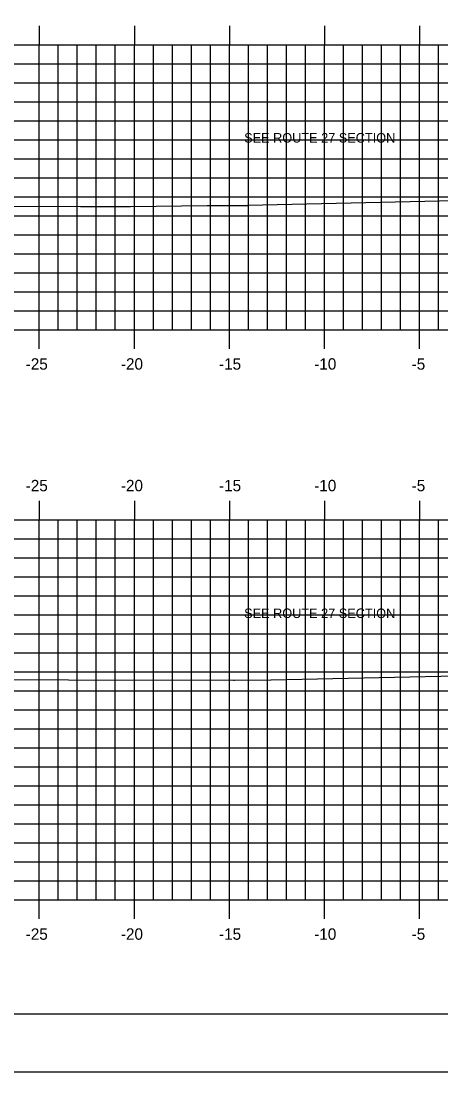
# Model space of a CAD drawing. Extents: x 1048343 to 1048513, y 781387 to 781497.
# Drawn here: x 1048400.2 to 1048422.3, y 781387.3 to 781442.6 of the extents above; entities that cross this region are included whole.
import ezdxf

# ---------------------------------------------------------------- set-up
doc = ezdxf.new("R2010")
doc.units = 0
for name, color, linetype in [('ANNOTATION', 7, 'Continuous'), ('BORDER', 7, 'Continuous'), ('H_V ANNOTATION', 7, 'Continuous'), ('MAJOR', 7, 'Continuous'), ('MINOR', 7, 'Continuous'), ('PLOT BOUNDARY', 7, 'Continuous'), ('S_Roadway_Centerline', 7, 'Continuous')]:
    doc.layers.add(name, color=color, linetype=linetype)

msp = doc.modelspace()

# ---------------------------------------------------------------- linework, layer by layer
at = {"layer": 'BORDER'}
msp.add_lwpolyline([(1048351.12, 781390.375), (1048511.12, 781390.375), (1048511.12, 781495.375), (1048351.12, 781495.375)], close=True, dxfattribs=at)
at = {"layer": 'MAJOR'}
for p, q in [((1048401.119, 781442.377), (1048401.119, 781441.375)), ((1048406.119, 781442.377), (1048406.119, 781441.375)), ((1048411.119, 781442.377), (1048411.119, 781441.375)), ((1048416.119, 781442.377), (1048416.119, 781441.375)), ((1048421.119, 781442.377), (1048421.119, 781441.375)), ((1048356.119, 781441.375), (1048496.119, 781441.375)), ((1048356.119, 781441.375), (1048496.119, 781441.375)), ((1048401.119, 781426.375), (1048401.119, 781441.375)), ((1048406.119, 781426.375), (1048406.119, 781441.375)), ((1048411.119, 781426.375), (1048411.119, 781441.375)), ((1048416.119, 781426.375), (1048416.119, 781441.375)), ((1048421.119, 781426.375), (1048421.119, 781441.375)), ((1048356.119, 781436.375), (1048496.119, 781436.375)), ((1048356.119, 781431.375), (1048496.119, 781431.375)), ((1048356.119, 781426.375), (1048496.119, 781426.375)), ((1048356.119, 781426.375), (1048496.119, 781426.375)), ((1048401.119, 781425.373), (1048401.119, 781426.375)), ((1048406.119, 781425.373), (1048406.119, 781426.375)), ((1048411.119, 781425.373), (1048411.119, 781426.375)), ((1048416.119, 781425.373), (1048416.119, 781426.375)), ((1048421.119, 781425.373), (1048421.119, 781426.375)), ((1048401.119, 781417.377), (1048401.119, 781416.375)), ((1048406.119, 781417.377), (1048406.119, 781416.375)), ((1048411.119, 781417.377), (1048411.119, 781416.375)), ((1048416.119, 781417.377), (1048416.119, 781416.375)), ((1048421.119, 781417.377), (1048421.119, 781416.375)), ((1048356.119, 781416.375), (1048496.119, 781416.375)), ((1048356.119, 781416.375), (1048496.119, 781416.375)), ((1048401.119, 781396.375), (1048401.119, 781416.375)), ((1048406.119, 781396.375), (1048406.119, 781416.375)), ((1048411.119, 781396.375), (1048411.119, 781416.375)), ((1048416.119, 781396.375), (1048416.119, 781416.375)), ((1048421.119, 781396.375), (1048421.119, 781416.375)), ((1048356.119, 781411.375), (1048496.119, 781411.375)), ((1048356.119, 781406.375), (1048496.119, 781406.375)), ((1048356.119, 781401.375), (1048496.119, 781401.375)), ((1048356.119, 781396.375), (1048496.119, 781396.375)), ((1048356.119, 781396.375), (1048496.119, 781396.375)), ((1048401.119, 781395.373), (1048401.119, 781396.375)), ((1048406.119, 781395.373), (1048406.119, 781396.375)), ((1048411.119, 781395.373), (1048411.119, 781396.375)), ((1048416.119, 781395.373), (1048416.119, 781396.375)), ((1048421.119, 781395.373), (1048421.119, 781396.375))]:
    msp.add_line(p, q, dxfattribs=at)
at = {"layer": 'MINOR'}
for p, q in [((1048402.119, 781426.375), (1048402.119, 781441.375)), ((1048403.119, 781426.375), (1048403.119, 781441.375)), ((1048404.119, 781426.375), (1048404.119, 781441.375)), ((1048405.119, 781426.375), (1048405.119, 781441.375)), ((1048407.119, 781426.375), (1048407.119, 781441.375)), ((1048408.119, 781426.375), (1048408.119, 781441.375)), ((1048409.119, 781426.375), (1048409.119, 781441.375)), ((1048410.119, 781426.375), (1048410.119, 781441.375)), ((1048412.119, 781426.375), (1048412.119, 781441.375)), ((1048413.119, 781426.375), (1048413.119, 781441.375)), ((1048414.119, 781426.375), (1048414.119, 781441.375)), ((1048415.119, 781426.375), (1048415.119, 781441.375)), ((1048417.119, 781426.375), (1048417.119, 781441.375)), ((1048418.119, 781426.375), (1048418.119, 781441.375)), ((1048419.119, 781426.375), (1048419.119, 781441.375)), ((1048420.119, 781426.375), (1048420.119, 781441.375)), ((1048422.119, 781426.375), (1048422.119, 781441.375)), ((1048356.119, 781440.375), (1048496.119, 781440.375)), ((1048356.119, 781439.375), (1048496.119, 781439.375)), ((1048356.119, 781438.375), (1048496.119, 781438.375)), ((1048356.119, 781437.375), (1048496.119, 781437.375)), ((1048356.119, 781435.375), (1048496.119, 781435.375)), ((1048356.119, 781434.375), (1048496.119, 781434.375)), ((1048356.119, 781433.375), (1048496.119, 781433.375)), ((1048356.119, 781432.375), (1048496.119, 781432.375)), ((1048356.119, 781430.375), (1048496.119, 781430.375)), ((1048356.119, 781429.375), (1048496.119, 781429.375)), ((1048356.119, 781428.375), (1048496.119, 781428.375)), ((1048356.119, 781427.375), (1048496.119, 781427.375)), ((1048402.119, 781396.375), (1048402.119, 781416.375)), ((1048403.119, 781396.375), (1048403.119, 781416.375)), ((1048404.119, 781396.375), (1048404.119, 781416.375)), ((1048405.119, 781396.375), (1048405.119, 781416.375)), ((1048407.119, 781396.375), (1048407.119, 781416.375)), ((1048408.119, 781396.375), (1048408.119, 781416.375)), ((1048409.119, 781396.375), (1048409.119, 781416.375)), ((1048410.119, 781396.375), (1048410.119, 781416.375)), ((1048412.119, 781396.375), (1048412.119, 781416.375)), ((1048413.119, 781396.375), (1048413.119, 781416.375)), ((1048414.119, 781396.375), (1048414.119, 781416.375)), ((1048415.119, 781396.375), (1048415.119, 781416.375)), ((1048417.119, 781396.375), (1048417.119, 781416.375)), ((1048418.119, 781396.375), (1048418.119, 781416.375)), ((1048419.119, 781396.375), (1048419.119, 781416.375)), ((1048420.119, 781396.375), (1048420.119, 781416.375)), ((1048422.119, 781396.375), (1048422.119, 781416.375)), ((1048356.119, 781415.375), (1048496.119, 781415.375)), ((1048356.119, 781414.375), (1048496.119, 781414.375)), ((1048356.119, 781413.375), (1048496.119, 781413.375)), ((1048356.119, 781412.375), (1048496.119, 781412.375)), ((1048356.119, 781410.375), (1048496.119, 781410.375)), ((1048356.119, 781409.375), (1048496.119, 781409.375)), ((1048356.119, 781408.375), (1048496.119, 781408.375)), ((1048356.119, 781407.375), (1048496.119, 781407.375)), ((1048356.119, 781405.375), (1048496.119, 781405.375)), ((1048356.119, 781404.375), (1048496.119, 781404.375)), ((1048356.119, 781403.375), (1048496.119, 781403.375)), ((1048356.119, 781402.375), (1048496.119, 781402.375)), ((1048356.119, 781400.375), (1048496.119, 781400.375)), ((1048356.119, 781399.375), (1048496.119, 781399.375)), ((1048356.119, 781398.375), (1048496.119, 781398.375)), ((1048356.119, 781397.375), (1048496.119, 781397.375))]:
    msp.add_line(p, q, dxfattribs=at)
at = {"layer": 'PLOT BOUNDARY'}
msp.add_lwpolyline([(1048343.026, 781387.316), (1048513.026, 781387.316), (1048513.026, 781497.316), (1048343.026, 781497.316)], close=True, dxfattribs=at)
at = {"layer": 'S_Roadway_Centerline'}
for points in [[(1048397.517, 781432.883), (1048403.278, 781432.868), (1048405.917, 781432.863), (1048409.959, 781432.912), (1048412.069, 781432.919), (1048412.094, 781432.924), (1048422.166, 781433.153), (1048425.802, 781433.232), (1048427.73, 781433.216), (1048440.46, 781433.006), (1048445.704, 781432.939), (1048447.573, 781432.913), (1048447.942, 781433.407), (1048448.084, 781433.576), (1048449.937, 781433.508), (1048453.059, 781433.386), (1048457.596, 781433.784), (1048467.65, 781434.721), (1048470.236, 781434.963), (1048489.197, 781435.231), (1048493.877, 781435.266), (1048494.113, 781435.27), (1048495.01, 781435.311), (1048496.119, 781435.359)], [(1048399.613, 781407.977), (1048402.647, 781407.956), (1048411.34, 781407.93), (1048411.383, 781407.938), (1048413.295, 781407.949), (1048413.31, 781407.951), (1048426.292, 781408.232), (1048434.905, 781408.164), (1048440.786, 781408.065), (1048443.314, 781408.033), (1048448.081, 781407.963), (1048448.249, 781408.188), (1048448.606, 781408.615), (1048453.217, 781408.447), (1048453.503, 781408.435), (1048456.104, 781408.663), (1048463.623, 781409.324), (1048469.353, 781409.735), (1048471.95, 781409.995), (1048473.076, 781410.039), (1048489.208, 781410.246), (1048494.663, 781410.314), (1048496.119, 781410.415)]]:
    msp.add_lwpolyline(points, dxfattribs=at)

# ---------------------------------------------------------------- texts
at = {"layer": 'ANNOTATION'}
for p in [(1048411.896, 781436.226), (1048411.896, 781411.206)]:
    msp.add_text('SEE ROUTE 27 SECTION', height=0.5, dxfattribs=at).set_placement(p)
at = {"layer": 'H_V ANNOTATION'}
for s, p in [('-25', (1048400.405, 781424.275)), ('-20', (1048405.413, 781424.275)), ('-15', (1048410.576, 781424.275)), ('-10', (1048415.584, 781424.275)), ('-5', (1048420.71, 781424.275)), ('-25', (1048400.405, 781417.875)), ('-20', (1048405.413, 781417.875)), ('-15', (1048410.576, 781417.875)), ('-10', (1048415.584, 781417.875)), ('-5', (1048420.71, 781417.875)), ('-25', (1048400.405, 781394.275)), ('-20', (1048405.413, 781394.275)), ('-15', (1048410.576, 781394.275)), ('-10', (1048415.584, 781394.275)), ('-5', (1048420.71, 781394.275))]:
    msp.add_text(s, height=0.6, dxfattribs=at).set_placement(p)

doc.saveas('drawing.dxf')
